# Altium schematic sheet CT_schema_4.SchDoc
size 362 x 192 mm
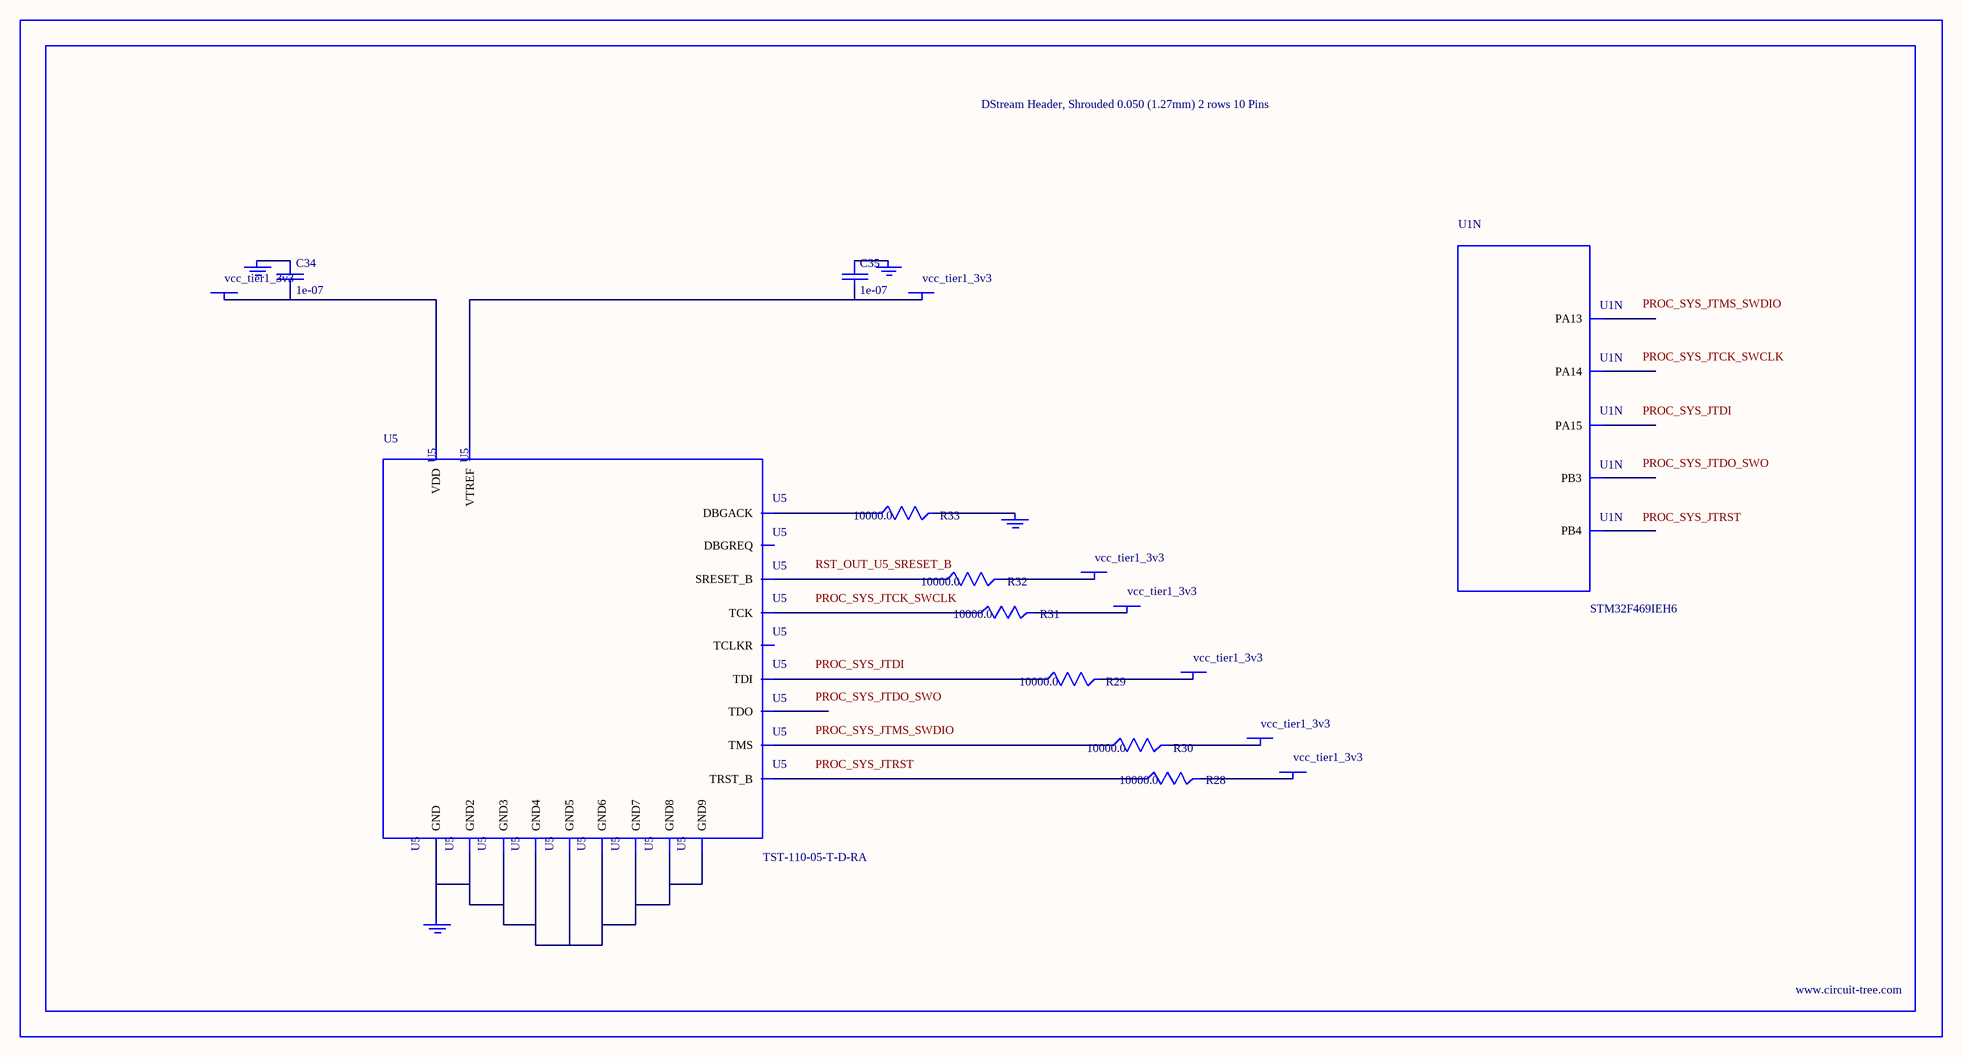
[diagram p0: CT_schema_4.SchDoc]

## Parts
BORDER3  (no value)
C34  1e-07  [C0402]
C35  1e-07  [C0402]
GND_INSTANCE_3_0  (no value)
GND_INSTANCE_3_1  (no value)
GND_INSTANCE_3_2  (no value)
GND_INSTANCE_3_3  (no value)
POWER_INSTANCE_3_0  vcc_tier1_3v3
POWER_INSTANCE_3_1  vcc_tier1_3v3
POWER_INSTANCE_3_2  vcc_tier1_3v3
POWER_INSTANCE_3_3  vcc_tier1_3v3
POWER_INSTANCE_3_4  vcc_tier1_3v3
POWER_INSTANCE_3_5  vcc_tier1_3v3
POWER_INSTANCE_3_6  vcc_tier1_3v3
R28  10000.0  [R0603]
R29  10000.0  [R0603]
R30  10000.0  [R0603]
R31  10000.0  [R0603]
R32  10000.0  [R0603]
R33  10000.0  [R0603]
U1  STM32F469IEH6  [UFBGA176]  (part N of 16)
U5  TST-110-05-T-D-RA  [TST-110-05-T-D-RA]

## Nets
NetC34_1: C34.1 GND_INSTANCE_3_1.0(GND)
NetC34_2: C34.2 POWER_INSTANCE_3_1.0(PWR) U5.2(VDD)
NetC35_1: C35.1 GND_INSTANCE_3_0.0(GND)
NetC35_2: C35.2 POWER_INSTANCE_3_0.0(PWR) U5.1(VTREF)
NetGND_INSTANCE_3_2_0: GND_INSTANCE_3_2.0(GND) R33.2
NetGND_INSTANCE_3_3_0: GND_INSTANCE_3_3.0(GND) U5.4(GND) U5.6(GND2) U5.8(GND3) U5.10(GND4) U5.12(GND5) U5.14(GND6) U5.16(GND7) U5.18(GND8) U5.20(GND9)
NetPOWER_INSTANCE_3_2_0: POWER_INSTANCE_3_2.0(PWR) R28.2
NetPOWER_INSTANCE_3_3_0: POWER_INSTANCE_3_3.0(PWR) R29.2
NetPOWER_INSTANCE_3_4_0: POWER_INSTANCE_3_4.0(PWR) R30.2
NetPOWER_INSTANCE_3_5_0: POWER_INSTANCE_3_5.0(PWR) R31.2
NetPOWER_INSTANCE_3_6_0: POWER_INSTANCE_3_6.0(PWR) R32.2
NetR28_1: R28.1 U5.3(TRST_B)
NetR29_1: R29.1 U5.5(TDI)
NetR30_1: R30.1 U5.7(TMS)
NetR31_1: R31.1 U5.9(TCK)
NetR32_1: R32.1 U5.15(SRESET_B)
NetR33_1: R33.1 U5.19(DBGACK)

Not connected (* = marked no-connect by the designer): U1 A9(PB4) A10(PB3) A13(PA15) A14(PA14) A15(PA13); U5 11(TCLKR) 13(TDO) 17(DBGREQ)

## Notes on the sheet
- Labels drawn without touching a wire or pin: PROC_SYS_JTCK_SWCLK, PROC_SYS_JTDI, PROC_SYS_JTDO_SWO, PROC_SYS_JTMS_SWDIO, PROC_SYS_JTRST, RST_OUT_U5_SRESET_B

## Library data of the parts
BORDER3 = BORDER_PAGE3
C34 C35 = C0402C104K3RACTU
GND_INSTANCE_3_0-GND_INSTANCE_3_3 = GND
POWER_INSTANCE_3_0-POWER_INSTANCE_3_6 = PWR
R28-R33 = RC0603JR-0710KL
